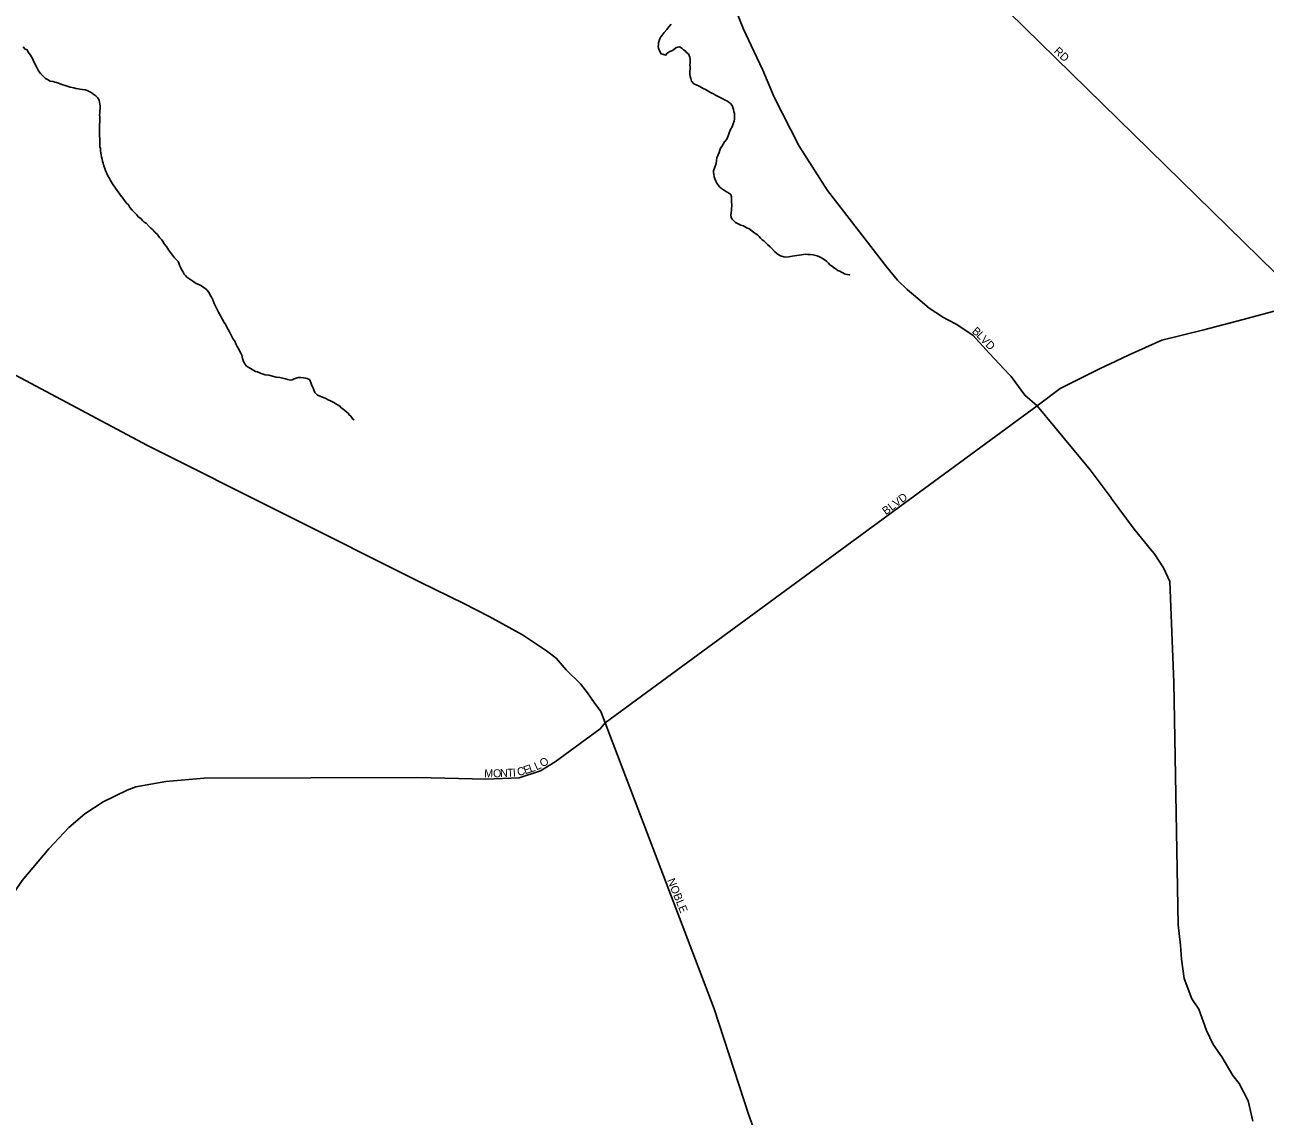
# Model space of a CAD drawing. Extents: x 2139079 to 2262683, y 1235796 to 1334992.
# Drawn here: x 2227269 to 2235020, y 1285350 to 1292167 of the extents above; entities that cross this region are included whole.
import ezdxf

# ---------------------------------------------------------------- set-up
doc = ezdxf.new("R2010")
doc.units = 0
for name, color, linetype in [('GM_X_City_Street', 7, 'Continuous'), ('GM_X_City_Street_Text', 7, 'Continuous'), ('GM_X_Minor_River', 7, 'Continuous')]:
    doc.layers.add(name, color=color, linetype=linetype)

msp = doc.modelspace()

# ---------------------------------------------------------------- linework, layer by layer
at = {"layer": 'GM_X_City_Street'}
for points in [[(2237139.1, 1283818.1), (2237013.6, 1286565.2), (2236914.8, 1287903.6), (2236898.9, 1288051.7), (2236904.4, 1288071.9), (2236952, 1288095.2), (2237028.2, 1288171.5), (2237100.3, 1288249.6), (2237206.3, 1288419), (2237198.5, 1288487), (2237161.7, 1288590.5), (2237128, 1288653.8), (2237061.6, 1288738.4), (2236872.5, 1288918.2), (2236470.3, 1289275.2), (2235905.5, 1289792.5), (2235277.5, 1290426.7), (2232535.6, 1293111.5)], [(2231467.3, 1293027.3), (2231479.1, 1293008.7), (2231523.7, 1292913.5), (2231558.2, 1292818), (2231643.4, 1292470.8), (2231700.2, 1292291.6), (2231760.2, 1292140.6), (2231823.9, 1292001.7), (2231881.1, 1291884.8), (2231951.7, 1291715.9), (2232108, 1291408.8), (2232285.6, 1291132.3), (2232654.9, 1290654), (2232723.2, 1290571.4), (2232782.8, 1290512.8), (2232848.4, 1290458.2), (2232920.1, 1290397.9), (2233009.9, 1290338), (2233033.1, 1290326.3), (2233036, 1290324.8)], [(2233595.7, 1289787), (2233739.2, 1289895.1), (2233988.7, 1290020), (2234081.8, 1290064.5), (2234168.9, 1290104.9), (2234373.1, 1290196.5), (2234636.1, 1290261.6), (2234883.1, 1290326.2), (2235130, 1290392.8), (2235277.5, 1290426.7)], [(2233036, 1290324.8), (2233093.2, 1290295.9), (2233195.3, 1290226.3), (2233294.4, 1290116.4), (2233421.9, 1289980.8), (2233422.4, 1289980.3)], [(2231890.5, 1285085.7), (2231793.3, 1285356.2), (2231577.6, 1286021.1), (2231177.5, 1287070.6), (2230895.8, 1287806.1), (2230867.9, 1287877.6), (2230826.3, 1287934.8), (2230784.7, 1287993.9), (2230741.1, 1288051), (2230652.7, 1288137.1), (2230589.6, 1288210.1), (2230529.8, 1288256.1), (2230378.1, 1288357.4), (2230170.8, 1288471.9), (2230012.3, 1288552.1), (2229740.2, 1288685.6), (2228035.8, 1289538.9), (2226954.2, 1290113.2)], [(2233422.4, 1289980.3), (2233432.5, 1289969.5), (2233517.7, 1289853.2), (2233595.7, 1289787), (2233926.8, 1289388), (2234056.8, 1289212.5)], [(2226635.6, 1285956.3), (2226703.4, 1286013.5), (2226860.1, 1286232.3), (2227103.2, 1286604), (2227251.9, 1286822.6), (2227419.3, 1287019.6), (2227544.1, 1287153.4), (2227644.2, 1287238.2), (2227758.5, 1287313.5), (2227909.1, 1287385.6), (2227962.6, 1287407.1), (2228150.3, 1287440), (2228390.3, 1287462.3), (2229723.6, 1287464.6), (2230151, 1287455.6), (2230359.3, 1287463), (2230492.5, 1287506.6), (2230583.3, 1287563.1), (2230677.8, 1287631.8), (2230864.7, 1287769.1), (2230895.8, 1287806.1), (2233595.7, 1289787)], [(2234056.8, 1289212.5), (2234057.7, 1289211.3), (2234201.1, 1289017.7), (2234312.3, 1288880.5), (2234313.6, 1288878.8)], [(2234313.6, 1288878.8), (2234325.3, 1288864.4), (2234383.8, 1288775.5), (2234424.1, 1288690.3), (2234448.4, 1288058.6), (2234475.5, 1286545.7), (2234490.9, 1286417.6), (2234497.1, 1286331.5), (2234514.3, 1286209.5), (2234561.7, 1286082.2), (2234605.4, 1286019.1), (2234653, 1285885.8), (2234695.4, 1285798.6), (2234749.5, 1285721.7), (2234816.7, 1285605), (2234856.1, 1285553.9), (2234913, 1285444.9), (2234942.3, 1285319.2)]]:
    msp.add_lwpolyline(points, dxfattribs=at)
at = {"layer": 'GM_X_Minor_River'}
for points in [[(2231307.8, 1292172), (2231294.1, 1292153.7), (2231280.4, 1292137.3), (2231264.7, 1292118.9), (2231251, 1292102.6), (2231243.2, 1292092.4), (2231235.5, 1292076.2), (2231229.9, 1292054), (2231228.2, 1292041.9), (2231226.3, 1292031.8), (2231228.6, 1292021.8), (2231235, 1292003.8), (2231245.4, 1291986), (2231275.6, 1291978.5), (2231281.4, 1291988.7), (2231299.3, 1292001.1), (2231311.2, 1292005.3), (2231325.1, 1292013.6), (2231337, 1292023.9), (2231348.9, 1292028.1), (2231360.9, 1292030.4), (2231375.2, 1292020.6), (2231385.4, 1292010.8), (2231395.6, 1292004.9), (2231405.9, 1291993.1)], [(2227258.6, 1292029.5), (2227270.9, 1292015.7), (2227283.1, 1292009.9), (2227289.3, 1292000), (2227297.6, 1291988.1), (2227305.8, 1291978.2), (2227312.1, 1291966.3), (2227318.3, 1291956.4), (2227322.5, 1291946.4), (2227326.7, 1291936.4), (2227333, 1291924.5), (2227337.2, 1291914.5), (2227343.4, 1291904.6), (2227354, 1291878.7), (2227366.4, 1291862.9), (2227399.1, 1291831.3), (2227411.3, 1291825.6), (2227427.6, 1291815.8), (2227445.7, 1291812.2), (2227457.8, 1291808.4), (2227467.9, 1291806.6), (2227480, 1291802.8), (2227496.2, 1291797.1), (2227506.3, 1291793.2), (2227522.5, 1291787.5), (2227540.7, 1291781.8), (2227552.8, 1291778.1), (2227564.9, 1291776.3), (2227575, 1291772.5), (2227589.2, 1291768.7), (2227603.3, 1291767), (2227613.3, 1291765.2), (2227629.4, 1291763.5), (2227645.5, 1291761.8), (2227659.7, 1291756), (2227671.9, 1291750.2), (2227684.1, 1291744.4), (2227694.2, 1291736.6), (2227712.6, 1291722.9), (2227722.8, 1291713), (2227733.2, 1291697.2), (2227737.7, 1291671.1), (2227740, 1291661.1), (2227740.3, 1291645.1), (2227738.6, 1291629), (2227738.8, 1291618.9), (2227737.1, 1291602.8), (2227737.3, 1291592.8), (2227737.6, 1291578.7), (2227737.8, 1291568.7), (2227738, 1291558.6), (2227736.3, 1291544.5), (2227736.7, 1291528.5), (2227735.3, 1291498.3), (2227735.6, 1291482.2), (2227735.8, 1291470.2), (2227738.1, 1291458.2), (2227738.3, 1291446.1), (2227738.7, 1291430.1), (2227738.9, 1291416), (2227739.2, 1291404), (2227741.4, 1291394), (2227741.7, 1291381.9), (2227744, 1291365.9), (2227746.2, 1291355.9), (2227748.5, 1291341.9), (2227752.8, 1291327.9), (2227755.1, 1291313.9), (2227759.3, 1291301.9), (2227763.7, 1291285.9), (2227770, 1291269.9), (2227774.3, 1291258), (2227778.6, 1291246), (2227784.8, 1291234.1), (2227789, 1291224.1), (2227799.5, 1291206.2), (2227805.7, 1291194.3), (2227811.9, 1291184.4)], [(2231405.9, 1291993.1), (2231416.1, 1291985.2), (2231424.5, 1291965.3), (2231426.8, 1291951.3), (2231427, 1291939.2), (2231427.3, 1291927.2), (2231425.5, 1291915.1), (2231425.8, 1291903.1), (2231426, 1291891), (2231424.3, 1291876.9), (2231424.7, 1291858.8), (2231427, 1291844.8), (2231431.3, 1291830.8), (2231435.6, 1291814.8), (2231450, 1291799.1), (2231464.2, 1291791.3), (2231482.4, 1291783.6), (2231496.6, 1291775.8), (2231508.8, 1291770.1), (2231523, 1291762.3), (2231543.3, 1291750.6), (2231557.5, 1291742.9), (2231571.8, 1291735.1), (2231586, 1291727.3), (2231630.6, 1291704.1), (2231644.8, 1291696.3), (2231655, 1291692.5), (2231669.2, 1291684.8), (2231679.4, 1291674.9), (2231689.7, 1291663.1), (2231694, 1291651.1), (2231698.3, 1291637.1), (2231700.5, 1291625.1), (2231702.8, 1291613.1), (2231703.1, 1291599), (2231703.5, 1291578.9), (2231701.7, 1291564.8), (2231696, 1291548.7), (2231688.4, 1291530.4), (2231678.7, 1291512.2), (2231671.1, 1291491.9), (2231663.4, 1291473.7), (2231655.8, 1291453.5), (2231642.1, 1291437.1), (2231632.4, 1291420.9), (2231624.6, 1291406.6), (2231616.8, 1291396.4), (2231611.1, 1291384.3), (2231607.3, 1291370.2), (2231599.7, 1291349.9), (2231594, 1291335.8), (2231590.3, 1291319.6), (2231588.6, 1291301.5), (2231581.1, 1291277.2), (2231573.5, 1291255), (2231571.7, 1291244.9), (2231573.9, 1291234.9), (2231576.3, 1291216.9), (2231580.6, 1291204.9), (2231586.9, 1291190.9), (2231593.2, 1291177), (2231603.5, 1291163.2), (2231611.8, 1291153.3), (2231621.9, 1291145.4), (2231634.2, 1291135.6), (2231648.4, 1291127.9), (2231662.6, 1291120.1), (2231681, 1291106.4), (2231685.3, 1291092.4), (2231685.5, 1291080.4), (2231685.8, 1291068.3), (2231686, 1291056.3), (2231686.2, 1291046.2), (2231686.5, 1291034.2), (2231684.7, 1291022.1), (2231685, 1291010), (2231683.3, 1290991.9), (2231681.6, 1290977.8), (2231683.9, 1290963.8), (2231690.1, 1290953.9), (2231698.3, 1290944), (2231710.6, 1290932.2), (2231726.9, 1290924.4), (2231743.1, 1290914.7), (2231759.3, 1290911), (2231769.4, 1290905.2), (2231779.6, 1290899.4), (2231793.7, 1290895.6), (2231812.1, 1290879.9), (2231824.3, 1290870.1), (2231836.6, 1290862.3), (2231846.8, 1290854.4), (2231857, 1290844.6), (2231867.2, 1290834.8), (2231877.5, 1290824.9), (2231887.7, 1290817.1), (2231910.2, 1290795.4), (2231926.6, 1290779.6), (2231936.8, 1290769.8), (2231953.3, 1290752), (2231967.6, 1290738.2)], [(2227811.9, 1291184.4), (2227818.2, 1291174.4), (2227851.3, 1291126.9), (2227859.5, 1291115), (2227865.8, 1291105.1), (2227878.1, 1291091.2), (2227892.6, 1291069.4), (2227905, 1291053.6), (2227917.3, 1291041.8), (2227925.6, 1291025.8), (2227940, 1291010.1), (2227952.3, 1290996.2), (2227968.7, 1290980.5), (2227977, 1290968.6), (2227987.2, 1290960.7), (2227997.4, 1290954.9), (2228005.6, 1290945), (2228015.8, 1290935.2), (2228028, 1290927.4), (2228046.5, 1290907.6), (2228056.7, 1290897.8), (2228067, 1290887.9), (2228081.4, 1290872.1), (2228097.7, 1290856.4), (2228104, 1290846.5), (2228112.2, 1290836.6), (2228122.5, 1290826.7), (2228130.7, 1290816.8), (2228141.1, 1290799), (2228155.5, 1290783.2), (2228168, 1290761.3), (2228186.6, 1290735.6), (2228205.1, 1290711.8), (2228219.5, 1290698), (2228227.7, 1290688.1), (2228231.9, 1290678.2), (2228236.2, 1290666.2), (2228242.5, 1290652.3), (2228248.8, 1290638.3), (2228257.1, 1290626.4), (2228265.4, 1290610.5), (2228273.7, 1290600.6), (2228281.9, 1290590.7), (2228318.5, 1290565.3), (2228340.9, 1290551.7), (2228357.1, 1290544), (2228373.4, 1290536.3), (2228383.6, 1290528.4), (2228393.7, 1290522.6), (2228406, 1290510.8), (2228420.4, 1290493), (2228426.7, 1290479), (2228435.1, 1290465.1), (2228443.4, 1290449.2), (2228451.9, 1290427.3), (2228466.6, 1290397.4), (2228479.1, 1290371.6), (2228504.2, 1290325.8), (2228514.6, 1290307.9), (2228524.9, 1290292.1), (2228531.2, 1290278.1), (2228547.9, 1290250.3), (2228554.2, 1290236.4), (2228562.5, 1290220.5), (2228570.9, 1290202.6), (2228581.2, 1290190.7), (2228587.6, 1290174.8), (2228596, 1290156.8), (2228606.3, 1290141), (2228612.6, 1290127), (2228618.9, 1290117.1), (2228625.2, 1290103.2), (2228627.4, 1290093.2), (2228629.6, 1290083.2), (2228633.8, 1290071.2), (2228640.2, 1290055.2), (2228654.7, 1290035.4), (2228668.9, 1290025.7), (2228711.6, 1290002.4), (2228723.7, 1289998.6), (2228735.8, 1289992.8), (2228752, 1289987.1), (2228772.2, 1289981.4), (2228794.4, 1289977.9), (2228816.6, 1289972.3), (2228840.8, 1289966.7), (2228863, 1289963.1), (2228889.2, 1289957.6), (2228899.2, 1289955.8), (2228913.4, 1289952), (2228929.5, 1289948.3), (2228939.6, 1289948.5), (2228951.4, 1289956.8), (2228977.4, 1289963.3), (2228993.5, 1289963.6), (2229011.6, 1289962), (2229023.7, 1289960.2), (2229033.7, 1289958.4), (2229050, 1289948.6), (2229060.6, 1289920.7), (2229066.9, 1289906.8)], [(2231967.6, 1290738.2), (2231979.8, 1290730.4), (2231992, 1290724.7), (2232012.2, 1290717), (2232024.3, 1290715.2), (2232042.3, 1290717.6), (2232064.3, 1290722), (2232122.4, 1290731.2), (2232134.4, 1290731.4), (2232146.4, 1290733.7), (2232160.5, 1290731.9), (2232176.6, 1290732.2), (2232194.7, 1290730.6), (2232220.9, 1290723.1), (2232235.1, 1290717.3), (2232247.3, 1290711.5), (2232263.5, 1290701.8), (2232279.9, 1290688), (2232290.1, 1290678.2), (2232300.4, 1290668.3), (2232310.5, 1290662.5), (2232328.9, 1290646.8), (2232339.1, 1290641), (2232349.3, 1290633.1), (2232361.4, 1290627.3), (2232371.6, 1290621.5), (2232381.7, 1290617.7), (2232391.9, 1290611.8), (2232408, 1290608.1), (2232420.1, 1290606.4), (2232424.1, 1290606.4), (2232420.1, 1290606.4)], [(2229066.9, 1289906.8), (2229073.2, 1289892.8), (2229077.5, 1289880.9), (2229081.7, 1289870.9), (2229098.1, 1289853.1), (2229114.3, 1289847.4), (2229150.8, 1289832.1), (2229165, 1289824.3), (2229179.1, 1289818.6), (2229199.5, 1289806.9), (2229213.7, 1289799.1), (2229227.9, 1289791.4), (2229238.1, 1289785.5), (2229246.3, 1289775.6), (2229256.5, 1289767.8), (2229270.8, 1289756), (2229289.2, 1289740.3), (2229295.4, 1289730.4), (2229305.6, 1289722.6), (2229318, 1289704.7), (2229328.2, 1289698.9)]]:
    msp.add_lwpolyline(points, dxfattribs=at)

# ---------------------------------------------------------------- texts
at = {"layer": 'GM_X_City_Street_Text'}
for s, rotation, p in [('RD', 317.1199, (2233695.7, 1291997.5)), ('B', 318.72954, (2233183.8, 1290247.6)), ('L', 314.5364, (2233212.8, 1290222.1)), ('V', 313.77916, (2233237.4, 1290197.2)), ('D', 313.77916, (2233267.9, 1290165.4)), ('BLVD', 36.57772, (2232649.7, 1289103)), ('O', 31.819, (2230504.9, 1287527.3)), ('M', 357.99619, (2230139.1, 1287467.4)), ('O', 2.56341, (2230196.3, 1287465.6)), ('N', 2.58586, (2230240.2, 1287467.5)), ('T', 2.60347, (2230284.2, 1287469.5)), ('I', 3.79023, (2230320.5, 1287471.2)), ('C', 14.15764, (2230352.2, 1287474.2)), ('E', 18.58538, (2230394.7, 1287485)), ('L', 18.68858, (2230428.1, 1287496.3)), ('L', 24.18605, (2230466.4, 1287509.5)), ('NOBLE', 292.03879, (2231282.4, 1286824.2))]:
    msp.add_text(s, height=50, rotation=rotation, dxfattribs=at).set_placement(p)

doc.saveas('drawing.dxf')
